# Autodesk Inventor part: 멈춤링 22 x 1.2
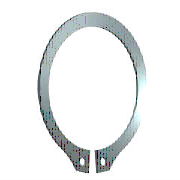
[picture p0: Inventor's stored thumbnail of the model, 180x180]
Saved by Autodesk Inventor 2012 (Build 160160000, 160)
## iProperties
IsCustomPart: 0
Company: 한국ATC센터
Created: 2014-07
Part Number: 멈춤링 22 x 1.2
Material: Steel, Mild
Description: 리테이닝 링(C형)
Document SubType Name: Modeling
Standard: KS B 1336
Designer: KYOUNG IL JANG
Standards Organization: KS
Language: ko-KR
Size Designation: 22 x 1.2
Categories: <MemberInstance><Categories><Category DisplayName="샤프트 부품" InternalName="7f7aeb1f-a693-4053-b835-cee3144e0d98" Mnemonic="SHFT"><Category DisplayName="써클립" Inter
Density: 7.86 g/cm^3
Mass: 1.8286 g
Surface Area: 5.91219 cm^2
Volume: 0.232646 cm^3
Author: KYOUNG IL JANG
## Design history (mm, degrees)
sketch "스케치1"
  geometry: L1 (-6, 0)-(6, 0) reference; L2 (0, 20.189)-(0, -80.536) reference; L3 (-48.09, 0)-(48.09, 0) reference; L4 (-0.5, -21.488)-(-0.5, -25.588); L5 (-0.5, -6.54)-(-0.5, -13.29); L6 (-2.795, 2.7)-(3.672, 2.7); L7 (0.5, -6.54)-(0.5, -13.29); L8 (0.5, -21.488)-(0.5, -25.588); C1 r 1 at (-2, -23.437); C2 r 1 at (2, -23.437); A1 r 10.5 centre (0, -11) between (0.5, -21.488) and (-0.5, -21.488); A2 r 13.025 centre (0, -10.325) between (5.149, -22.289) and (-5.149, -22.289); A3 r 14.597 centre (0, -11) between (-2.318, -25.411) and (-0.5, -25.588); A4 r 2 centre (-2, -23.437) between (-3.97, -23.781) and (-2.318, -25.411); A5 r 2 centre (-5.94, -24.126) between (-3.97, -23.781) and (-5.149, -22.289); A6 r 2 centre (5.94, -24.126) between (5.149, -22.289) and (3.97, -23.781); A7 r 2 centre (2, -23.437) between (2.318, -25.411) and (3.97, -23.781); A8 r 14.597 centre (0, -11) between (0.5, -25.588) and (2.318, -25.411)
  constraints: 16 point on circle, 12 end point, 10 centre point, 9 symmetric about line, 5 point on line, 4 tangent, 3 coincident, 2 horizontal, 1 perpendicular, 1 vertical, 5 other
  dimensions: "d0" = 21 diameter of A1 (= ND); "d1" = 4.1 distance of L4.end L4.start (= SRB2); "d6" = 0.5 distance between parallel lines of L2 L5 (= 0.25 x SD5); "d7" = 2.7 distance between parallel lines of L6 L3 (= SRB1); "d8" = 0.675 distance of A1.centre A2.centre (= 0.25 x SRB1); "d9" = 2 radius of A4 (= SD5); "d10" = 2 radius of A5 (= SD5); "d11" = 1.5 distance from line of L4 A4.centre (= 0.75 x SD5); "d12" = 2 diameter of C1 (= SD5); "d13" = 2 diameter of C2 (= SD5); "d14" = 11 distance from line of A1.centre L1 (= 0.5 x WD)
extrude "본체" new body sketch "스케치1" distance "d2" = 1.2 (= SD); taper "d3" = 0 deg
workaxis "Work Axis1"
workplane "Work Plane1"
body "Solid1"
other parameters: "WD" = 22 (= WDMIN) [user parameter; used in 1 equation term], "SD" = 1.2 [user parameter; used in 1 equation term], "SRB1" = 2.7 [user parameter; used in 2 equation terms], "ND" = 21 [user parameter; used in 1 equation term], "SRB2" = 4.1 [user parameter; used in 1 equation term], "SD5" = 2 [user parameter; used in 6 equation terms], "d15" = 0, "d16" = 0, "d17" = 0, "d41" = 0, "d42" = 0, "WDMIN" = 22 [user parameter; used in 1 equation term], "SD3" = 20.5 [user parameter], "WDMAX" = 24 [user parameter]
